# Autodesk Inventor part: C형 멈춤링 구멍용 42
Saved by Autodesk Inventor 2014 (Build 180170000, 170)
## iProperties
Created: 2026-04
Part Number: C형 멈춤링 구멍용 42
Material: 강철, 연강
Document SubType Name: Modeling
Designer: dg
Density: 7.86 g/cm^3
Appearance: 강철
Mass: 5.3944 g
Surface Area: 12.2623 cm^2
Volume: 0.68631 cm^3
Author: jhkim
Description: 리테이닝 링(C형)
Creation Date: 2026-03-27
Sending System: Autodesk Inventor 2026
Preprocessor: ST-DEVELOPER v20.1
Author: dg
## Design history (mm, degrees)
node "C형 멈춤링 구멍용 421"
body "Solid1"
node "기준1"
